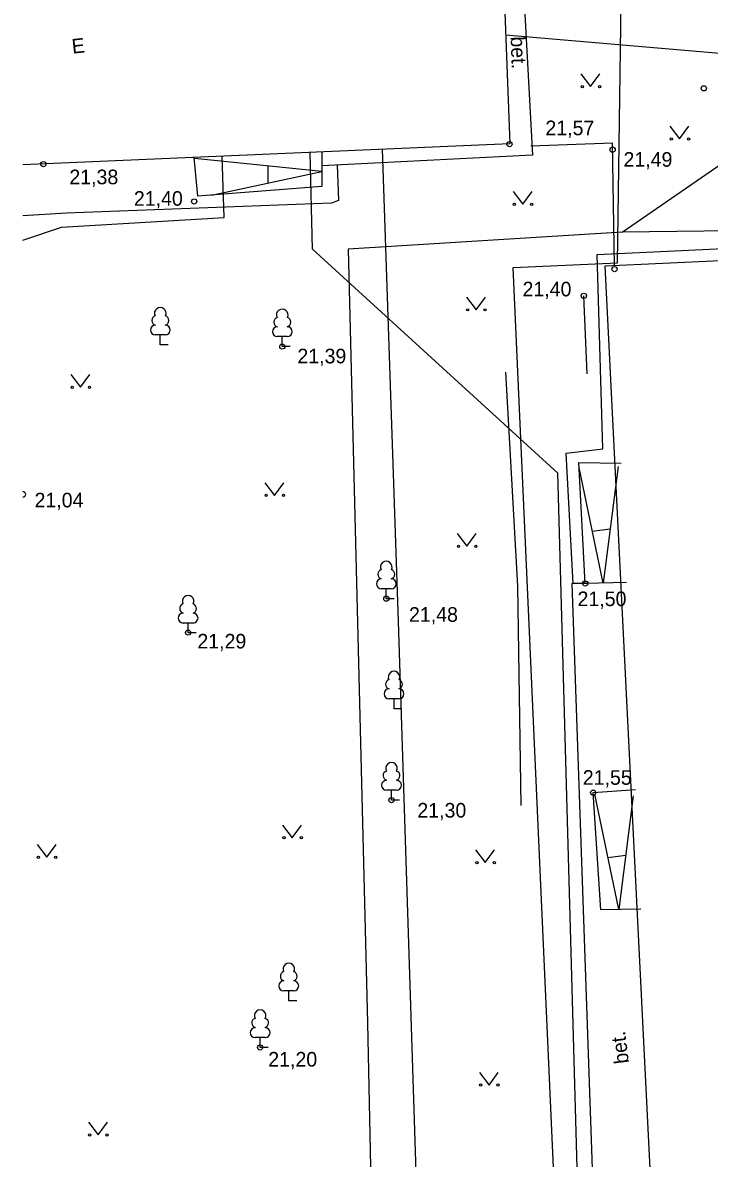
# Model space of a CAD drawing. Extents: x 714038 to 714279, y 6589845 to 6590041.
# Drawn here: x 714037.8 to 714070.7, y 6589933.2 to 6589987.6 of the extents above; entities that cross this region are included whole.
import ezdxf

# ---------------------------------------------------------------- set-up
doc = ezdxf.new("R2010")
doc.units = 0
for name, color, linetype in [('AED', 7, 'Continuous'), ('HALJASTUS', 7, 'Continuous'), ('HOONE', 7, 'Continuous'), ('HOONEDET', 7, 'Continuous'), ('KORGUS', 7, 'Continuous'), ('MPKAABEL', 7, 'Continuous'), ('PUU', 7, 'Continuous'), ('SITRASS', 7, 'Continuous'), ('TEE', 7, 'Continuous'), ('Слой 1', 7, 'Continuous')]:
    doc.layers.add(name, color=color, linetype=linetype)

msp = doc.modelspace()

# ---------------------------------------------------------------- linework, layer by layer
at = {"layer": 'AED'}
msp.add_lwpolyline([(714066.147, 6589975.927), (714066.05, 6589981.78), (714062.15, 6589981.64)], dxfattribs=at)
at = {"layer": 'HALJASTUS'}
for p, q in [((714064.543, 6589985.103), (714065.006, 6589984.496)), ((714065.006, 6589984.496), (714065.452, 6589985.103)), ((714068.803, 6589982.593), (714069.266, 6589981.987)), ((714069.266, 6589981.987), (714069.712, 6589982.593)), ((714061.297, 6589979.467), (714061.76, 6589978.86)), ((714061.76, 6589978.86), (714062.206, 6589979.467)), ((714059.057, 6589974.407), (714059.52, 6589973.8)), ((714059.52, 6589973.8), (714059.966, 6589974.407)), ((714040.117, 6589970.697), (714040.58, 6589970.09)), ((714040.58, 6589970.09), (714041.026, 6589970.697)), ((714049.407, 6589965.517), (714049.87, 6589964.91)), ((714049.87, 6589964.91), (714050.316, 6589965.517)), ((714058.617, 6589963.077), (714059.08, 6589962.47)), ((714059.08, 6589962.47), (714059.526, 6589963.077)), ((714050.257, 6589949.117), (714050.72, 6589948.51)), ((714050.72, 6589948.51), (714051.166, 6589949.117)), ((714038.497, 6589948.177), (714038.96, 6589947.57)), ((714038.96, 6589947.57), (714039.406, 6589948.177)), ((714059.497, 6589947.927), (714059.96, 6589947.32)), ((714059.96, 6589947.32), (714060.406, 6589947.927)), ((714059.677, 6589937.267), (714060.14, 6589936.66)), ((714060.14, 6589936.66), (714060.586, 6589937.267)), ((714040.957, 6589934.877), (714041.42, 6589934.27)), ((714041.42, 6589934.27), (714041.866, 6589934.877))]:
    msp.add_line(p, q, dxfattribs=at)
for points in [[(714064.84, 6589970.74), (714064.68, 6589974.47)], [(714061.68, 6589950.05), (714061.52, 6589960.56), (714060.95, 6589970.82)]]:
    msp.add_lwpolyline(points, dxfattribs=at)
for centre, radius in [((714064.605, 6589984.496), 0.055), ((714065.434, 6589984.496), 0.055), ((714070.425, 6589984.412), 0.125), ((714068.865, 6589981.987), 0.055), ((714069.694, 6589981.987), 0.055), ((714061.359, 6589978.86), 0.055), ((714062.188, 6589978.86), 0.055), ((714059.119, 6589973.8), 0.055), ((714059.948, 6589973.8), 0.055), ((714040.179, 6589970.09), 0.055), ((714041.008, 6589970.09), 0.055), ((714049.469, 6589964.91), 0.055), ((714050.298, 6589964.91), 0.055), ((714058.679, 6589962.47), 0.055), ((714059.508, 6589962.47), 0.055), ((714050.319, 6589948.51), 0.055), ((714051.148, 6589948.51), 0.055), ((714038.559, 6589947.57), 0.055), ((714039.388, 6589947.57), 0.055), ((714059.559, 6589947.32), 0.055), ((714060.388, 6589947.32), 0.055), ((714059.739, 6589936.66), 0.055), ((714060.568, 6589936.66), 0.055), ((714041.019, 6589934.27), 0.055), ((714041.848, 6589934.27), 0.055)]:
    msp.add_circle(centre, radius, dxfattribs=at)
at = {"layer": 'HOONE'}
for points in [[(714049.068, 6589991.791), (714049.048, 6589992.294), (714051.589, 6589992.446), (714051.611, 6589991.89), (714060.739, 6589992.247), (714061.143, 6589981.755), (714037.81, 6589980.739)], [(714076.752, 6589976.421), (714079.42, 6589915.82), (714068.72, 6589915.35), (714065.699, 6589975.906), (714076.752, 6589976.421)]]:
    msp.add_lwpolyline(points, dxfattribs=at)
at = {"layer": 'HOONEDET'}
for points in [[(714061.859, 6589987.966), (714062.226, 6589981.203), (714052.13, 6589980.7)], [(714052.13, 6589981.36), (714052.13, 6589979.7), (714046.2, 6589979.24), (714046.02, 6589981.1)], [(714046.85, 6589979.29), (714052.13, 6589980.43), (714046.03, 6589981.05)], [(714049.57, 6589979.88), (714049.57, 6589980.69)], [(714064.17, 6589960.69), (714063.83, 6589966.94), (714065.59, 6589967.14), (714065.32, 6589976.45), (714077.437, 6589977.031), (714077.942, 6589968.099)], [(714066.72, 6589960.73), (714064.75, 6589960.69), (714064.44, 6589966.49), (714066.47, 6589966.45)], [(714066.32, 6589966.29), (714065.6, 6589960.71), (714064.45, 6589966.24)], [(714065.08, 6589963.2), (714065.94, 6589963.31)], [(714067.41, 6589945.09), (714065.5, 6589945.05), (714065.13, 6589950.67), (714067.16, 6589950.82)], [(714067.05, 6589950.52), (714066.35, 6589945.07), (714065.2, 6589950.6)], [(714065.83, 6589947.56), (714066.69, 6589947.67)]]:
    msp.add_lwpolyline(points, dxfattribs=at)
at = {"layer": 'KORGUS'}
for centre in [(714061.12, 6589981.74), (714066.06, 6589981.47), (714038.8, 6589980.78), (714046.02, 6589978.99), (714066.15, 6589975.75), (714064.68, 6589974.47), (714050.24, 6589972.04), (714064.75, 6589960.69), (714055.22, 6589959.96), (714045.73, 6589958.34), (714055.47, 6589950.31), (714065.13, 6589950.67), (714049.18, 6589938.46)]:
    msp.add_circle(centre, 0.125, dxfattribs=at)
msp.add_arc((714037.83, 6589964.96), 0.125, 260.931, 99.069, dxfattribs=at)
at = {"layer": 'MPKAABEL'}
for points in [[(714064.57, 6589925.22), (714063.43, 6589965.97), (714051.68, 6589976.71), (714051.58, 6589981.34)], [(714037.81, 6589977.143), (714039.66, 6589977.76), (714047.46, 6589978.22), (714047.36, 6589981.15)]]:
    msp.add_lwpolyline(points, dxfattribs=at)
at = {"layer": 'PUU'}
for p, q in [((714044.64, 6589972.595), (714044.16, 6589972.595)), ((714044.4, 6589972.12), (714044.4, 6589972.595)), ((714044.78, 6589972.12), (714044.4, 6589972.12)), ((714050.48, 6589972.515), (714050, 6589972.515)), ((714050.24, 6589972.04), (714050.24, 6589972.515)), ((714050.62, 6589972.04), (714050.24, 6589972.04)), ((714055.46, 6589960.435), (714054.98, 6589960.435)), ((714055.22, 6589959.96), (714055.22, 6589960.435)), ((714055.6, 6589959.96), (714055.22, 6589959.96)), ((714045.97, 6589958.795), (714045.49, 6589958.795)), ((714045.73, 6589958.32), (714045.73, 6589958.795)), ((714046.11, 6589958.32), (714045.73, 6589958.32)), ((714055.83, 6589955.165), (714055.35, 6589955.165)), ((714055.59, 6589954.69), (714055.59, 6589955.165)), ((714055.97, 6589954.69), (714055.59, 6589954.69)), ((714055.71, 6589950.785), (714055.23, 6589950.785)), ((714055.47, 6589950.31), (714055.47, 6589950.785)), ((714055.85, 6589950.31), (714055.47, 6589950.31)), ((714050.79, 6589941.175), (714050.31, 6589941.175)), ((714050.55, 6589940.7), (714050.55, 6589941.175)), ((714050.93, 6589940.7), (714050.55, 6589940.7)), ((714049.42, 6589938.935), (714048.94, 6589938.935)), ((714049.18, 6589938.46), (714049.18, 6589938.935)), ((714049.56, 6589938.46), (714049.18, 6589938.46))]:
    msp.add_line(p, q, dxfattribs=at)
for centre, radius, start, end in [((714044.4, 6589973.64), 0.277, 332.5799, 207.4201), ((714050.24, 6589973.56), 0.277, 332.5799, 207.4201), ((714044.23, 6589973.293), 0.233, 109.0217, 253.1415), ((714044.57, 6589973.293), 0.233, 286.8508, 70.9859), ((714050.07, 6589973.213), 0.233, 109.0217, 253.1415), ((714050.41, 6589973.213), 0.233, 286.8508, 70.9859), ((714044.163, 6589972.832), 0.238, 90.0016, 269.3953), ((714044.637, 6589972.832), 0.238, 270.6047, 89.9984), ((714050.003, 6589972.752), 0.238, 90.0016, 269.3953), ((714050.477, 6589972.752), 0.238, 270.6047, 89.9984), ((714055.22, 6589961.48), 0.277, 332.5799, 207.4201), ((714055.05, 6589961.133), 0.233, 109.0217, 253.1415), ((714055.39, 6589961.133), 0.233, 286.8508, 70.9859), ((714054.983, 6589960.672), 0.238, 90.0016, 269.3953), ((714055.457, 6589960.672), 0.238, 270.6047, 89.9984), ((714045.73, 6589959.84), 0.277, 332.5799, 207.4201), ((714045.56, 6589959.493), 0.233, 109.0217, 253.1415), ((714045.9, 6589959.493), 0.233, 286.8508, 70.9859), ((714045.493, 6589959.032), 0.238, 90.0016, 269.3953), ((714045.967, 6589959.032), 0.238, 270.6047, 89.9984), ((714055.59, 6589956.21), 0.277, 332.5799, 207.4201), ((714055.42, 6589955.863), 0.233, 109.0217, 253.1415), ((714055.76, 6589955.863), 0.233, 286.8508, 70.9859), ((714055.353, 6589955.402), 0.238, 90.0016, 269.3953), ((714055.827, 6589955.402), 0.238, 270.6047, 89.9984), ((714055.47, 6589951.83), 0.277, 332.5799, 207.4201), ((714055.3, 6589951.483), 0.233, 109.0217, 253.1415), ((714055.64, 6589951.483), 0.233, 286.8508, 70.9859), ((714055.233, 6589951.022), 0.238, 90.0016, 269.3953), ((714055.707, 6589951.022), 0.238, 270.6047, 89.9984), ((714050.55, 6589942.22), 0.277, 332.5799, 207.4201), ((714050.313, 6589941.412), 0.238, 90.0016, 269.3953), ((714050.38, 6589941.873), 0.233, 109.0217, 253.1415), ((714050.72, 6589941.873), 0.233, 286.8508, 70.9859), ((714050.787, 6589941.412), 0.238, 270.6047, 89.9984), ((714049.18, 6589939.98), 0.277, 332.5799, 207.4201), ((714049.01, 6589939.633), 0.233, 109.0217, 253.1415), ((714049.35, 6589939.633), 0.233, 286.8508, 70.9859), ((714048.943, 6589939.172), 0.238, 90.0016, 269.3953), ((714049.417, 6589939.172), 0.238, 270.6047, 89.9984)]:
    msp.add_arc(centre, radius, start, end, dxfattribs=at)
at = {"layer": 'SITRASS'}
for points in [[(714060.942, 6589986.97), (714077.9, 6589985.526)], [(714066.52, 6589977.52), (714077.87, 6589985.346)], [(714055.02, 6589981.49), (714055.79, 6589958.87), (714056.98, 6589921.53)], [(714075.371, 6589977.682), (714074.38, 6589977.623), (714066.51, 6589977.52), (714053.4, 6589976.7), (714054.32, 6589939.62), (714054.67, 6589922.8)]]:
    msp.add_lwpolyline(points, dxfattribs=at)
at = {"layer": 'TEE'}
for points in [[(714052.87, 6589980.74), (714052.93, 6589979.04), (714052.59, 6589978.91), (714039.9, 6589978.43), (714037.81, 6589978.303)], [(714064.85, 6589960.69), (714064.1, 6589960.69), (714065.23, 6589928.51), (714065.33, 6589925.52), (714066.27, 6589908.82), (714067.36, 6589908.2), (714066.82, 6589914.45), (714068.72, 6589914.66), (714068.68, 6589915.34)]]:
    msp.add_lwpolyline(points, dxfattribs=at)
at = {"layer": 'Слой 1'}
msp.add_lwpolyline([(714064.59, 6589902.42), (714061.29, 6589975.82), (714066.29, 6589976.05), (714066.53, 6589993.08), (714086, 6589982.93), (714087.46, 6589939.06), (714088.9, 6589899.98), (714072.76, 6589898.26)], close=True, dxfattribs=at)

# ---------------------------------------------------------------- texts
at = {"layer": 'HOONE'}
msp.add_text('E', height=0.7, rotation=5.9546, dxfattribs=at).set_placement((714040.194, 6589986.07))
at = {"layer": 'HOONEDET'}
msp.add_text('bet.', height=0.7, rotation=272.15, dxfattribs=at).set_placement((714061.172, 6589986.887))
at = {"layer": 'KORGUS'}
for s, p in [('21,57', (714062.841, 6589982.165)), ('21,49', (714066.579, 6589980.655)), ('21,38', (714040.044, 6589979.815)), ('21,40', (714043.134, 6589978.785)), ('21,40', (714061.744, 6589974.445)), ('21,39', (714050.964, 6589971.235)), ('21,04', (714038.376, 6589964.335)), ('21,50', (714064.379, 6589959.605)), ('21,48', (714056.309, 6589958.855)), ('21,29', (714046.174, 6589957.575)), ('21,55', (714064.631, 6589951.045)), ('21,30', (714056.709, 6589949.475)), ('21,20', (714049.569, 6589937.545))]:
    msp.add_text(s, height=0.7, dxfattribs=at).set_placement(p)
at = {"layer": 'TEE'}
msp.add_text('bet.', height=0.7, rotation=97.2047, dxfattribs=at).set_placement((714066.845, 6589937.723))

doc.saveas('drawing.dxf')
